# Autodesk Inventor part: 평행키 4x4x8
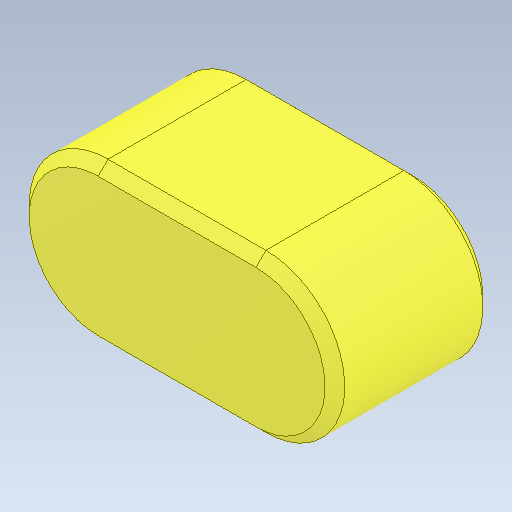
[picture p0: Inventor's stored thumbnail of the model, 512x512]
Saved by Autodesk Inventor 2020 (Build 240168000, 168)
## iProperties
Created: 2024-04
Part Number: 평행키 4x4x8
Material: 강철, 연강
Description: 평행 키
Document SubType Name: Modeling
Designer: oem
Density: 7.85 g/cm^3
Appearance: 기본값
Mass: 0.887151 g
Surface Area: 1.33212 cm^2
Volume: 0.113013 cm^3
Sending System: Autodesk Inventor 2025
Preprocessor: ST-DEVELOPER v20
Author: jhkim
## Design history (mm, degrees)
feature "Solid1"
node "솔리드1"
